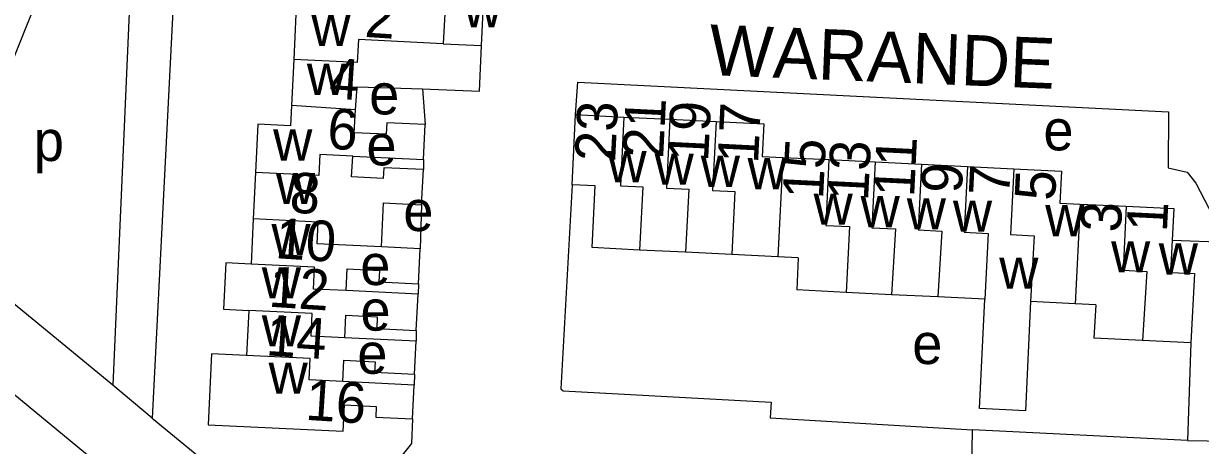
# Model space of a CAD drawing. Extents: x 163026 to 166241, y 382475 to 384501.
# Drawn here: x 164331.2 to 164447.4, y 383621.3 to 383663 of the extents above; entities that cross this region are included whole.
import ezdxf

# ---------------------------------------------------------------- set-up
doc = ezdxf.new("R2010")
doc.units = 0
for name, color, linetype in [('BLT_Basislijn', 7, 'Continuous'), ('BLT_Bebouwing', 7, 'Continuous'), ('BLT_Centroide', 7, 'Continuous'), ('BLT_Huisnummer', 7, 'Continuous'), ('BLT_Huisnummer_ tussenligend', 7, 'Continuous'), ('BLT_Onderverdeling_panden', 7, 'Continuous'), ('BLT_Straatnaam', 7, 'Continuous')]:
    doc.layers.add(name, color=color, linetype=linetype)

msp = doc.modelspace()

# ---------------------------------------------------------------- linework, layer by layer
at = {"layer": 'BLT_Basislijn'}
for p, q in [((164346.72, 383679.51), (164343.92, 383624)), ((164342.12, 383674.64), (164340.03, 383627.27)), ((164370.59, 383656.53), (164370.88, 383652.99)), ((164370.71, 383649.54), (164370.69, 383648.55)), ((164370.52, 383645.08), (164370.36, 383640.74)), ((164444.61, 383641.59), (164449.98, 383641.38)), ((164370.2, 383637.27), (164370.17, 383636.25)), ((164369.99, 383632.67), (164369.97, 383631.6)), ((164446.47, 383631.44), (164446.14, 383621.79)), ((164369.81, 383628.35), (164369.78, 383627.27)), ((164343.92, 383624), (164340.03, 383627.27)), ((164343.92, 383624), (164360.61, 383610.31)), ((164424.83, 383618.88), (164424.91, 383622.86)), ((164446.14, 383621.79), (164456.06, 383621.62))]:
    msp.add_line(p, q, dxfattribs=at)
for points in [[(164340.03, 383627.27), (164325.55, 383639.16), (164324.19, 383640.57), (164323.75, 383643.4), (164336.35, 383674.8)], [(164385.72, 383653.98), (164385.95, 383657.19), (164444.27, 383654.26), (164444.24, 383648.72), (164446.09, 383648.3), (164446.95, 383647.21), (164449.98, 383641.38)], [(164385.38, 383647.05), (164384.27, 383626.91), (164384.5, 383626.72), (164405.02, 383625.57), (164404.92, 383624.05), (164424.91, 383622.86)], [(164316.74, 383637.52), (164399.59, 383569.15), (164439.68, 383536.44), (164449.09, 383529.98), (164458.65, 383524.65), (164472.19, 383518.92), (164485.74, 383514.54), (164499.92, 383512), (164504.7, 383511.64), (164519.36, 383511.35), (164533, 383512.62), (164547.18, 383515.25), (164581.89, 383525.04), (164642.18, 383547.36), (164693.59, 383567.42), (164700, 383570.19), (164761.7, 383597.42), (164778.75, 383605.71), (164783.1, 383609.13), (164785.13, 383612.46), (164785.97, 383614.66), (164786.37, 383617.55)], [(164369.62, 383623.93), (164369.52, 383621.51), (164360.61, 383610.31)], [(164446.14, 383621.79), (164424.91, 383622.86)]]:
    msp.add_lwpolyline(points, dxfattribs=at)
at = {"layer": 'BLT_Bebouwing'}
for p, q in [((164357.9, 383659.43), (164357.67, 383654.87)), ((164370.71, 383649.54), (164370.88, 383652.99)), ((164385.38, 383647.05), (164385.72, 383653.98)), ((164385.72, 383653.98), (164390.49, 383653.74)), ((164390.49, 383653.74), (164395.04, 383653.52)), ((164395.04, 383653.52), (164399.59, 383653.29)), ((164399.59, 383653.29), (164404.31, 383653.06)), ((164404.31, 383653.06), (164404.15, 383649.86)), ((164404.15, 383649.86), (164406.17, 383649.76)), ((164406.17, 383649.76), (164410.73, 383649.54)), ((164410.73, 383649.54), (164415.29, 383649.31)), ((164354.12, 383648.28), (164353.9, 383643.68)), ((164370.52, 383645.08), (164370.69, 383648.55)), ((164415.29, 383649.31), (164419.86, 383649.08)), ((164419.86, 383649.08), (164424.42, 383648.86)), ((164424.42, 383648.86), (164428.98, 383648.63)), ((164428.98, 383648.63), (164433.68, 383648.4)), ((164433.68, 383648.4), (164433.53, 383645.25)), ((164433.53, 383645.25), (164435.54, 383645.15)), ((164435.54, 383645.15), (164440.09, 383644.93)), ((164353.9, 383643.68), (164353.68, 383639.21)), ((164370.36, 383640.74), (164366.55, 383640.92)), ((164370.2, 383637.27), (164370.36, 383640.74)), ((164396.58, 383640.39), (164392.03, 383640.61)), ((164401.13, 383640.16), (164396.58, 383640.39)), ((164405.68, 383639.94), (164401.13, 383640.16)), ((164407.71, 383639.84), (164405.68, 383639.94)), ((164407.71, 383639.84), (164407.55, 383636.67)), ((164412.43, 383636.42), (164407.55, 383636.67)), ((164369.99, 383632.67), (164370.17, 383636.25)), ((164416.91, 383636.2), (164412.43, 383636.42)), ((164421.5, 383635.99), (164416.91, 383636.2)), ((164426.11, 383635.75), (164421.5, 383635.99)), ((164435.06, 383635.31), (164430.65, 383635.53)), ((164353.46, 383634.65), (164353.24, 383630.19)), ((164437.07, 383635.21), (164435.06, 383635.31)), ((164437.07, 383635.21), (164436.9, 383631.91)), ((164369.81, 383628.35), (164369.97, 383631.6)), ((164441.69, 383631.67), (164436.9, 383631.91)), ((164446.47, 383631.44), (164441.69, 383631.67)), ((164369.62, 383623.93), (164369.78, 383627.27))]:
    msp.add_line(p, q, dxfattribs=at)
for points in [[(164361.47, 383666.14), (164358.23, 383666.29), (164358.11, 383663.91), (164357.9, 383659.43)], [(164376.42, 383660.8), (164376.59, 383664.18), (164374.6, 383664.28)], [(164370.59, 383656.53), (164376.22, 383656.28), (164376.42, 383660.8)], [(164364, 383654.46), (164364.15, 383656.73), (164370.59, 383656.53)], [(164357.67, 383654.87), (164357.58, 383652.87), (164354.35, 383653.03), (164354.12, 383648.28)], [(164370.88, 383652.99), (164367.07, 383653.18), (164367.02, 383652.04), (164363.85, 383652.19), (164364, 383654.46)], [(164370.69, 383648.55), (164366.77, 383648.74), (164366.72, 383647.67), (164363.6, 383647.82), (164363.71, 383649.88)], [(164363.71, 383649.88), (164370.71, 383649.54)], [(164392.03, 383640.61), (164387.34, 383640.85), (164387.64, 383646.94), (164385.38, 383647.05)], [(164366.55, 383640.92), (164366.76, 383645.26), (164370.52, 383645.08)], [(164440.09, 383644.93), (164444.77, 383644.7), (164444.61, 383641.59)], [(164444.61, 383641.59), (164444.46, 383638.39), (164446.81, 383638.28), (164446.47, 383631.44)], [(164353.68, 383639.21), (164351.19, 383639.33), (164350.97, 383634.78), (164353.46, 383634.65)], [(164363.07, 383636.6), (164363.18, 383638.74), (164366.35, 383638.59), (164366.3, 383637.46), (164370.2, 383637.27)], [(164370.17, 383636.25), (164363.07, 383636.6)], [(164430.65, 383635.53), (164430.13, 383624.74), (164425.59, 383624.96), (164426.11, 383635.75)], [(164362.92, 383631.94), (164363.02, 383634.17), (164366.14, 383634.02), (164366.09, 383632.86), (164369.99, 383632.67)], [(164369.97, 383631.6), (164362.92, 383631.94)], [(164353.24, 383630.19), (164349.77, 383630.36), (164349.43, 383623.36), (164362.77, 383622.71), (164362.9, 383625.32), (164366.04, 383625.17), (164365.99, 383624.1), (164369.62, 383623.93)], [(164362.74, 383627.61), (164362.84, 383629.72), (164365.93, 383629.57), (164365.88, 383628.54), (164369.81, 383628.35)], [(164369.78, 383627.27), (164362.74, 383627.61)]]:
    msp.add_lwpolyline(points, dxfattribs=at)
at = {"layer": 'BLT_Onderverdeling_panden'}
for p, q in [((164364, 383654.46), (164357.67, 383654.87)), ((164406.17, 383649.76), (164405.68, 383639.94)), ((164435.54, 383645.15), (164435.06, 383635.31))]:
    msp.add_line(p, q, dxfattribs=at)
for points in [[(164372.81, 383663.98), (164372.66, 383660.98)], [(164372.66, 383660.98), (164364.29, 383661.41), (164364.15, 383659.13), (164357.9, 383659.43)], [(164372.66, 383660.98), (164376.42, 383660.8)], [(164390.49, 383653.74), (164390.15, 383646.96), (164392.35, 383646.85), (164392.03, 383640.61)], [(164395.04, 383653.52), (164394.7, 383646.73), (164396.9, 383646.62), (164396.58, 383640.39)], [(164399.59, 383653.29), (164399.25, 383646.5), (164401.44, 383646.39), (164401.13, 383640.16)], [(164363.71, 383649.88), (164360.48, 383650.04), (164360.38, 383647.98), (164354.12, 383648.28)], [(164410.73, 383649.54), (164410.41, 383643.04), (164412.76, 383642.92), (164412.43, 383636.42)], [(164415.29, 383649.31), (164414.97, 383642.81), (164417.32, 383642.69), (164416.91, 383636.2)], [(164419.86, 383649.08), (164419.53, 383642.59), (164421.88, 383642.47), (164421.5, 383635.99)], [(164424.42, 383648.86), (164424.09, 383642.36), (164426.44, 383642.24), (164426.11, 383635.75)], [(164428.98, 383648.63), (164428.65, 383642.14), (164431, 383642.02), (164430.65, 383635.53)], [(164440.09, 383644.93), (164439.78, 383638.62), (164442.13, 383638.5), (164441.69, 383631.67)], [(164366.55, 383640.92), (164360.21, 383641.23), (164360.31, 383643.37), (164353.9, 383643.68)], [(164363.07, 383636.6), (164359.84, 383636.75), (164359.94, 383638.9), (164353.68, 383639.21)], [(164362.92, 383631.94), (164359.61, 383632.1), (164359.72, 383634.34), (164353.46, 383634.65)], [(164362.74, 383627.61), (164359.4, 383627.78), (164359.5, 383629.89), (164353.24, 383630.19)]]:
    msp.add_lwpolyline(points, dxfattribs=at)

# ---------------------------------------------------------------- texts
at = {"layer": 'BLT_Centroide'}
for s, p in [('w', (164374.62, 383662.59)), ('w', (164359.63, 383660.76)), ('w', (164359.19, 383655.93)), ('e', (164365.34, 383654)), ('e', (164431.91, 383650.45)), ('p', (164332.23, 383649.4)), ('w', (164355.86, 383649.44)), ('e', (164365.07, 383648.97)), ('w', (164388.86, 383647.3)), ('w', (164393.52, 383647.06)), ('w', (164398.08, 383646.84)), ('w', (164402.7, 383646.61)), ('w', (164356.13, 383645.15)), ('w', (164409.22, 383643.11)), ('w', (164413.86, 383642.86)), ('e', (164368.71, 383642.48)), ('w', (164418.42, 383642.64)), ('w', (164422.98, 383642.42)), ('w', (164432.09, 383641.97)), ('w', (164355.69, 383640.12)), ('w', (164438.59, 383638.41)), ('w', (164443.3, 383638.19)), ('e', (164364.46, 383637.15)), ('w', (164427.55, 383636.78)), ('w', (164354.74, 383635.83)), ('e', (164364.48, 383632.65)), ('w', (164354.74, 383631.09)), ('e', (164418.96, 383629.35)), ('e', (164364.17, 383628.39)), ('w', (164355.41, 383626.42))]:
    msp.add_text(s, height=4, dxfattribs=at).set_placement(p)
at = {"layer": 'BLT_Huisnummer'}
for s, rotation, p in [('2', 356.3019, (164364.83, 383661.66)), ('6', 356.3019, (164361.12, 383650.64)), ('23', 87.1702, (164389.62, 383649.27)), ('17', 87.1702, (164403.73, 383649.1)), ('13', 87.1702, (164414.59, 383645.41)), ('9', 87.1702, (164423.84, 383646.16)), ('5', 87.1702, (164433.05, 383645.43)), ('1', 87.1702, (164444.1, 383642.34)), ('10', 356.3019, (164356, 383639.81)), ('16', 356.3019, (164358.97, 383623.85))]:
    msp.add_text(s, height=4, rotation=rotation, dxfattribs=at).set_placement(p)
at = {"layer": 'BLT_Huisnummer_ tussenligend'}
for s, rotation, p in [('4', 356.3019, (164361.31, 383655.6)), ('21', 87.1702, (164394.36, 383649.61)), ('19', 87.1702, (164398.8, 383649.28)), ('15', 87.1702, (164410.15, 383645.58)), ('11', 87.1702, (164419.14, 383645.78)), ('8', 356.3019, (164357.41, 383644.33)), ('7', 87.1702, (164428.53, 383645.91)), ('3', 87.1702, (164439.55, 383642.3)), ('12', 356.3019, (164355.34, 383635.02)), ('14', 356.3019, (164355.08, 383630.22))]:
    msp.add_text(s, height=4, rotation=rotation, dxfattribs=at).set_placement(p)
at = {"layer": 'BLT_Straatnaam'}
msp.add_text('WARANDE', height=5, rotation=357.707, dxfattribs=at).set_placement((164398.83, 383657.89))

doc.saveas('drawing.dxf')
